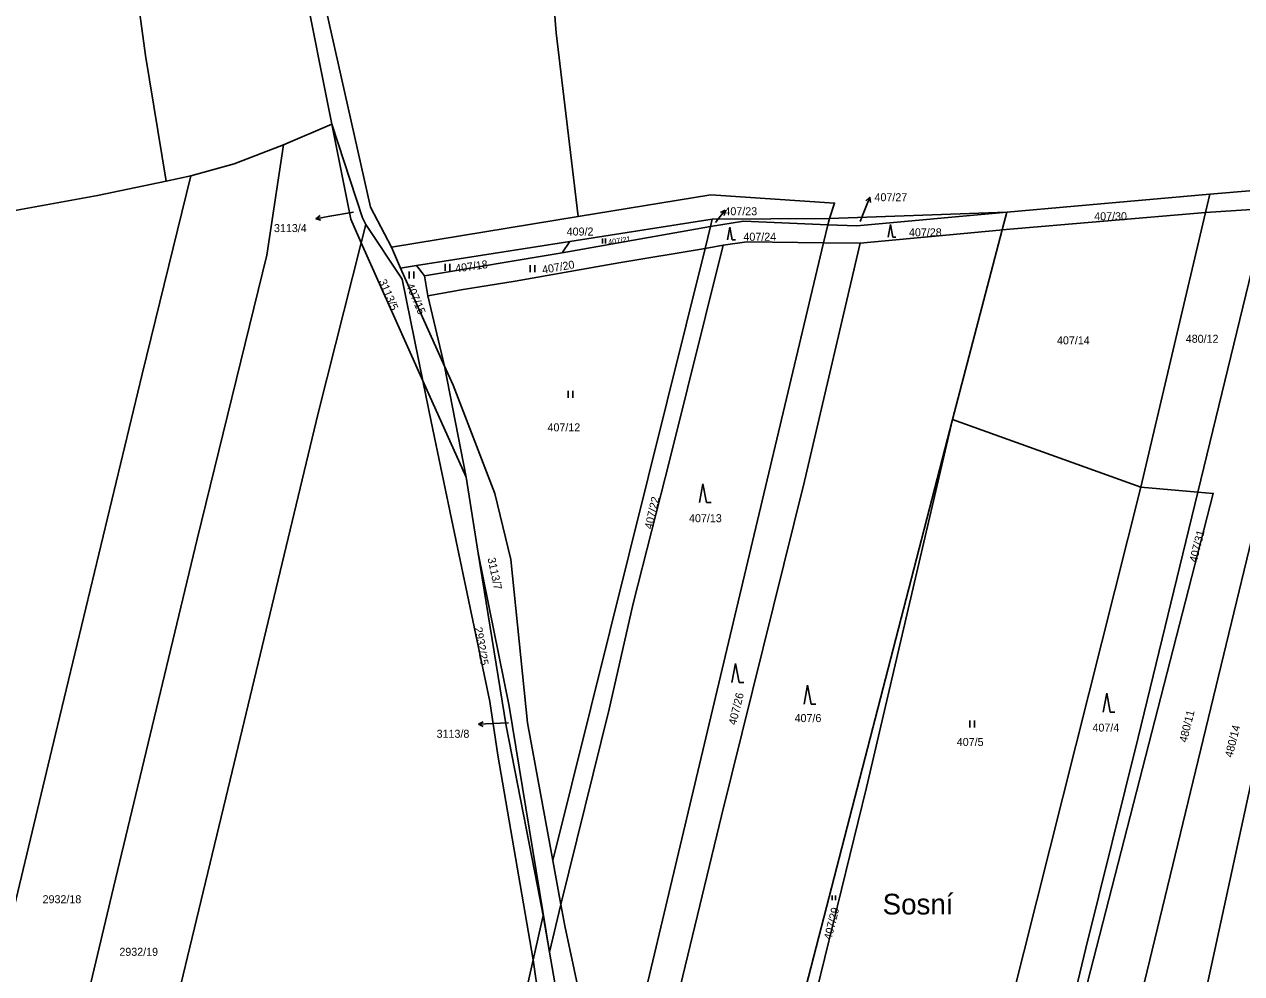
# Model space of a CAD drawing. Extents: x -755528 to -748832, y -1118122 to -1111095.
# Drawn here: x -753945.5 to -753686.9, y -1114157.4 to -1113955.7 of the extents above; entities that cross this region are included whole.
import ezdxf

# ---------------------------------------------------------------- set-up
doc = ezdxf.new("R2010")
doc.units = 0
for name, color, linetype in [('DZ_DO_PUPFL', 7, 'Continuous'), ('DZ_NAD_ZPF', 7, 'Continuous'), ('legenda barvy', 7, 'Continuous'), ('TZ_UMVŽST', 7, 'Continuous')]:
    doc.layers.add(name, color=color, linetype=linetype)

msp = doc.modelspace()

# ---------------------------------------------------------------- linework, layer by layer
at = {"layer": 'DZ_NAD_ZPF'}
for p, q in [((-753880.21, -1113976.91), (-753890.46, -1113981.25)), ((-753910.17, -1113987.88), (-753915.44, -1113988.98)), ((-753693.65, -1113991.74), (-753736.84, -1113995.56)), ((-753694.58, -1113995.67), (-753693.65, -1113991.74)), ((-753827.91, -1113996.51), (-753867.56, -1114002.99)), ((-753736.84, -1113995.56), (-753774.5, -1113996.92)), ((-753737.83, -1113999.35), (-753736.84, -1113995.56)), ((-753694.58, -1113995.67), (-753737.83, -1113999.35)), ((-753708.31, -1114054.03), (-753694.58, -1113995.67)), ((-753681.59, -1113994.82), (-753696.25, -1114055.07)), ((-753681.59, -1113994.82), (-753694.58, -1113995.67)), ((-753873.96, -1114002.11), (-753872.96, -1113998.18)), ((-753799.77, -1113998.63), (-753831.31, -1114004.2)), ((-753829.66, -1114001.83), (-753799.38, -1113997.08)), ((-753800.92, -1114003.27), (-753799.77, -1113998.63)), ((-753799.77, -1113998.63), (-753799.38, -1113997.08)), ((-753799.38, -1113997.08), (-753774.5, -1113996.92)), ((-753775.73, -1114002.11), (-753774.82, -1113998.27)), ((-753774.82, -1113998.27), (-753774.5, -1113996.92)), ((-753862.26, -1114006.94), (-753829.66, -1114001.83)), ((-753831.31, -1114004.2), (-753829.66, -1114001.83)), ((-753738.33, -1113999.39), (-753768, -1114002.15)), ((-753748.32, -1114039.61), (-753737.83, -1113999.35)), ((-753737.83, -1113999.35), (-753738.33, -1113999.39)), ((-753860.86, -1114031.42), (-753873.96, -1114002.11)), ((-753867.56, -1114002.99), (-753865.62, -1114007.47)), ((-753860.55, -1114009.1), (-753831.31, -1114004.2)), ((-753833.28, -1114133.35), (-753800.92, -1114003.27)), ((-753821.04, -1114192.61), (-753775.73, -1114002.11)), ((-753797.04, -1114002.61), (-753800.92, -1114003.27)), ((-753768, -1114002.15), (-753775.73, -1114002.11)), ((-753865.62, -1114007.47), (-753862.26, -1114006.94)), ((-753860.55, -1114009.1), (-753862.26, -1114006.94)), ((-753865.62, -1114007.47), (-753856.28, -1114028.27)), ((-753859.79, -1114013.37), (-753860.55, -1114009.1)), ((-753859.79, -1114013.37), (-753856.28, -1114028.27)), ((-753851.69, -1114051.91), (-753856.28, -1114028.27)), ((-753851.69, -1114051.91), (-753860.86, -1114031.42)), ((-753708.31, -1114054.03), (-753748.32, -1114039.61)), ((-753849.1, -1114068.02), (-753851.69, -1114051.91)), ((-753696.25, -1114055.07), (-753708.31, -1114054.03)), ((-753833.28, -1114133.35), (-753831.54, -1114142.69)), ((-753833.96, -1114152.83), (-753831.54, -1114142.69)), ((-753835.3, -1114145.03), (-753837.41, -1114154.43)), ((-753833.96, -1114152.83), (-753835.3, -1114145.03)), ((-753837.41, -1114154.43), (-753863.69, -1114271.17)), ((-753836.25, -1114162.79), (-753837.41, -1114154.43))]:
    msp.add_line(p, q, dxfattribs=at)
for points in [[(-753903.52, -1113823.18), (-753901.35, -1113846.36), (-753897.43, -1113881.42), (-753896.81, -1113888.95), (-753892.58, -1113905.57), (-753886.99, -1113927.7), (-753871.99, -1113994.49), (-753867.56, -1114002.99)], [(-753880.21, -1113976.91), (-753886.51, -1113945.21), (-753892.41, -1113919.97), (-753898.08, -1113900.3), (-753900.93, -1113881.86), (-753903.59, -1113846.87), (-753906.96, -1113826.83)], [(-753915.44, -1113988.98), (-753919.79, -1113962.33), (-753924.17, -1113929.95), (-753926.71, -1113905.18), (-753930.88, -1113875.47), (-753933.97, -1113845.34), (-753933.88, -1113834.39)], [(-753693.65, -1113991.74), (-753658.29, -1113988.76), (-753639.39, -1113995.23), (-753635.54, -1113991.72), (-753612.02, -1113882.78)], [(-753833.5, -1113922.82), (-753836.15, -1113922.97), (-753833.41, -1113946.72), (-753832.54, -1113957.5), (-753827.91, -1113996.51)], [(-753873.96, -1114002.11), (-753876.2, -1113997.09), (-753880.21, -1113976.91)], [(-753880.21, -1113976.91), (-753873.73, -1113996.81), (-753872.96, -1113998.18)], [(-753946.36, -1114222.18), (-753926.58, -1114139.03), (-753908.83, -1114065.02), (-753894.06, -1114004.7), (-753890.46, -1113981.25)], [(-753890.46, -1113981.25), (-753900.98, -1113985.32), (-753910.17, -1113987.88)], [(-753963.9, -1114211.19), (-753951.95, -1114160.75), (-753938.92, -1114106.48), (-753920.5, -1114030.03), (-753910.17, -1113987.88)], [(-753915.44, -1113988.98), (-753930, -1113992.06), (-753948.67, -1113995.43)], [(-753774.5, -1113996.92), (-753773.42, -1113993.65), (-753799.71, -1113991.9), (-753827.91, -1113996.51)], [(-753721.42, -1114217.18), (-753710.28, -1114170.24), (-753684.76, -1114064.89), (-753667.83, -1113993.57)], [(-753774.82, -1113998.27), (-753768.66, -1113998.5), (-753736.84, -1113995.56)], [(-753872.96, -1113998.18), (-753865.29, -1114009.83), (-753860.86, -1114031.42)], [(-753799.77, -1113998.63), (-753792.76, -1113997.48), (-753774.82, -1113998.27)], [(-753775.73, -1114002.11), (-753792.05, -1114001.91), (-753797.04, -1114002.61)], [(-753929.83, -1114232.54), (-753901.82, -1114116.18), (-753883.15, -1114038.26), (-753873.96, -1114002.11)], [(-753800.92, -1114003.27), (-753819.21, -1114006.38), (-753841.28, -1114010.23), (-753852.28, -1114012.02), (-753859.79, -1114013.37)], [(-753797.04, -1114002.61), (-753808.38, -1114048.1), (-753816.22, -1114078.69), (-753821.27, -1114101.16), (-753831.54, -1114142.69)], [(-753768, -1114002.15), (-753779.81, -1114052.73), (-753797.44, -1114123.84), (-753816.9, -1114204.45)], [(-753856.28, -1114028.27), (-753854.46, -1114032.33), (-753845.6, -1114055.34), (-753842.16, -1114069.39), (-753838.68, -1114104.1), (-753833.28, -1114133.35)], [(-753837.41, -1114154.43), (-753844.96, -1114110.91), (-753846.64, -1114099.52), (-753854.43, -1114062.43), (-753859.08, -1114040.06), (-753860.86, -1114031.42)], [(-753800.06, -1114249.13), (-753783.35, -1114175.05), (-753748.32, -1114039.61)], [(-753748.32, -1114039.61), (-753766.62, -1114117.83), (-753780.82, -1114175.62), (-753799.23, -1114251.42)], [(-753705.95, -1114214.41), (-753699.25, -1114182.95), (-753683.03, -1114108.23), (-753669.63, -1114046.38)], [(-753708.31, -1114054.03), (-753741.47, -1114185.71), (-753748.23, -1114213.51)], [(-753735.21, -1114215.01), (-753719.99, -1114151.98), (-753708.89, -1114107.17), (-753696.25, -1114055.07)], [(-753734.01, -1114215.18), (-753692.96, -1114055.35), (-753696.25, -1114055.07)], [(-753849.1, -1114068.02), (-753842.54, -1114100.53), (-753833.96, -1114152.83)], [(-753835.3, -1114145.03), (-753836.51, -1114138.78), (-753843.2, -1114104.73), (-753849.1, -1114068.02)], [(-753831.54, -1114142.69), (-753830.7, -1114147.21), (-753821.04, -1114192.61)], [(-753828.62, -1114180.76), (-753830.25, -1114174.42), (-753833.96, -1114152.83)]]:
    msp.add_lwpolyline(points, dxfattribs=at)
at = {"layer": 'legenda barvy'}
for p, q in [((-753767.02, -1113995.2), (-753765.896, -1113992.418)), ((-753765.896, -1113992.418), (-753766.735, -1113993.158)), ((-753765.896, -1113992.418), (-753765.807, -1113993.534)), ((-753883.615, -1113996.971), (-753882.716, -1113996.304)), ((-753880.66, -1113996.45), (-753883.615, -1113996.971)), ((-753875.63, -1113995.56), (-753880.66, -1113996.45)), ((-753798.5, -1113997.53), (-753796.652, -1113995.165)), ((-753796.652, -1113995.165), (-753797.664, -1113995.646)), ((-753796.652, -1113995.165), (-753796.874, -1113996.263)), ((-753767.97, -1113997.59), (-753767.02, -1113995.2)), ((-753883.615, -1113996.971), (-753882.542, -1113997.29)), ((-753798.67, -1113997.75), (-753798.5, -1113997.53)), ((-753849.057, -1114104.387), (-753848.083, -1114103.835)), ((-753846.06, -1114104.23), (-753849.057, -1114104.387)), ((-753849.057, -1114104.387), (-753848.031, -1114104.835)), ((-753842.71, -1114104.04), (-753846.06, -1114104.23))]:
    msp.add_line(p, q, dxfattribs=at)
at = {"layer": 'TZ_UMVŽST'}
for p, q in [((-753795.64, -1113998.79), (-753796.142, -1114001.47)), ((-753795.138, -1114001.47), (-753795.64, -1113998.79)), ((-753761.55, -1113998.23), (-753762.052, -1114000.91)), ((-753761.048, -1114000.91), (-753761.55, -1113998.23)), ((-753822.712, -1114002.21), (-753822.712, -1114001.205)), ((-753822.042, -1114002.21), (-753822.042, -1114001.205)), ((-753795.138, -1114001.47), (-753794.47, -1114001.47)), ((-753761.048, -1114000.91), (-753760.38, -1114000.91)), ((-753856.151, -1114008.06), (-753856.151, -1114006.56)), ((-753855.15, -1114008.06), (-753855.15, -1114006.56)), ((-753838.111, -1114008.31), (-753838.111, -1114006.81)), ((-753837.11, -1114008.31), (-753837.11, -1114006.81)), ((-753863.811, -1114009.7), (-753863.811, -1114008.2)), ((-753862.81, -1114009.7), (-753862.81, -1114008.2)), ((-753830.031, -1114035.01), (-753830.031, -1114033.51)), ((-753829.03, -1114035.01), (-753829.03, -1114033.51)), ((-753801.36, -1114053.27), (-753802.11, -1114057.27)), ((-753800.61, -1114057.27), (-753801.36, -1114053.27)), ((-753800.61, -1114057.27), (-753799.614, -1114057.27)), ((-753794.45, -1114091.5), (-753795.2, -1114095.5)), ((-753793.7, -1114095.5), (-753794.45, -1114091.5)), ((-753793.7, -1114095.5), (-753792.704, -1114095.5)), ((-753779.13, -1114096.09), (-753779.88, -1114100.09)), ((-753778.38, -1114100.09), (-753779.13, -1114096.09)), ((-753778.38, -1114100.09), (-753777.384, -1114100.09)), ((-753715.59, -1114097.8), (-753716.34, -1114101.8)), ((-753714.84, -1114101.8), (-753715.59, -1114097.8)), ((-753714.84, -1114101.8), (-753713.844, -1114101.8)), ((-753744.701, -1114105.09), (-753744.701, -1114103.59)), ((-753743.7, -1114105.09), (-753743.7, -1114103.59)), ((-753773.912, -1114141.75), (-753773.912, -1114140.745)), ((-753773.242, -1114141.75), (-753773.242, -1114140.745))]:
    msp.add_line(p, q, dxfattribs=at)

# ---------------------------------------------------------------- texts
at = {"layer": 'DZ_DO_PUPFL'}
for s, p in [('407/27', (-753764.92, -1113993.26)), ('407/23', (-753796.807, -1113996.24)), ('407/30', (-753718.24, -1113997.3)), ('3113/4', (-753892.505, -1113999.818)), ('409/2', (-753830.32, -1114000.55)), ('407/28', (-753757.6, -1114000.72)), ('407/24', (-753792.77, -1114001.65)), ('407/14', (-753726.15, -1114023.66)), ('480/12', (-753698.79, -1114023.33)), ('407/12', (-753834.4, -1114042.15)), ('407/13', (-753804.33, -1114061.45)), ('407/6', (-753781.9, -1114103.91)), ('407/4', (-753718.61, -1114105.94)), ('3113/8', (-753857.955, -1114107.248)), ('407/5', (-753747.44, -1114108.99)), ('2932/18', (-753941.67, -1114142.4)), ('2932/19', (-753925.36, -1114153.57))]:
    msp.add_text(s, height=1.7, dxfattribs=at).set_placement(p)
for s, height, rotation, p in [('407/21', 1.14, 9, (-753821.425, -1114002.537)), ('407/18', 1.7, 8, (-753853.871, -1114008.411)), ('407/20', 1.7, 10, (-753835.392, -1114008.687)), ('3113/5', 1.7, 293, (-753870.282, -1114010.242)), ('407/15', 1.7, 293, (-753864.492, -1114011.112)), ('407/22', 1.7, 77, (-753812.171, -1114063.031)), ('407/31', 1.7, 76, (-753696.445, -1114070.115)), ('3113/7', 1.7, 282, (-753847.141, -1114069.146)), ('2932/25', 1.7, 280, (-753849.957, -1114083.897)), ('407/26', 1.7, 76, (-753794.345, -1114104.655)), ('480/11', 1.7, 76, (-753698.585, -1114108.375)), ('480/14', 1.7, 76, (-753688.885, -1114111.545)), ('407/29', 1.7, 76, (-753774.075, -1114150.285))]:
    msp.add_text(s, height=height, rotation=rotation, dxfattribs=at).set_placement(p)
at = {"layer": 'legenda barvy'}
msp.add_text('Sosní', height=4.4, dxfattribs=at).set_placement((-753763.193, -1114144.79))

doc.saveas('drawing.dxf')
